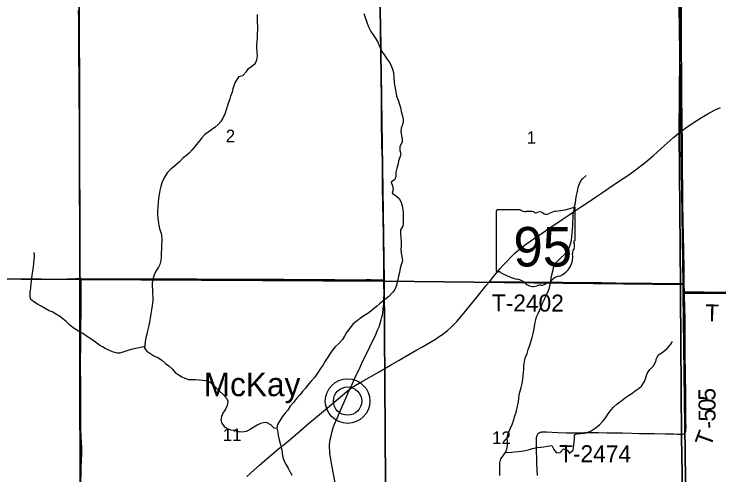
# Model space of a CAD drawing. Extents: x 1874609 to 2204689, y 815661 to 1281160.
# Drawn here: x 2033877 to 2046303, y 984416 to 992539 of the extents above; entities that cross this region are included whole.
import ezdxf

# ---------------------------------------------------------------- set-up
doc = ezdxf.new("R2010")
doc.units = 0
for name, color, linetype in [('GM_X_County_Road', 7, 'Continuous'), ('GM_X_Minor_River', 7, 'Continuous'), ('GM_X_Section', 7, 'Continuous'), ('GM_X_Section_Text', 7, 'Continuous'), ('GM_X_State_Location', 7, 'Continuous'), ('GM_X_State_Route', 7, 'Continuous'), ('GM_X_State_Shield', 7, 'Continuous'), ('GM_X_Township', 7, 'Continuous'), ('GM_X_Township_Road', 7, 'Continuous'), ('GM_X_Township_Road_Text', 7, 'Continuous'), ('GM_X_Unincorporated', 7, 'Continuous'), ('GM_X_Unincorporated_Location', 7, 'Continuous'), ('GM_X_Unincorporated_Text', 7, 'Continuous')]:
    doc.layers.add(name, color=color, linetype=linetype)

msp = doc.modelspace()

# ---------------------------------------------------------------- linework, layer by layer
at = {"layer": 'GM_X_County_Road'}
for points in [[(2033785, 987871), (2033999, 987869), (2034163, 987866), (2034261, 987865), (2034360, 987865), (2034441, 987864), (2034523, 987865), (2034670, 987868), (2034966, 987876), (2035031, 987876), (2035056, 987875)], [(2035056, 987875), (2035080, 987874), (2035179, 987872), (2035326, 987872), (2035457, 987872), (2035603, 987873), (2035766, 987874), (2035848, 987874), (2035930, 987874), (2036110, 987873), (2036241, 987871), (2036323, 987871), (2036438, 987870), (2036586, 987870), (2036766, 987871), (2036848, 987871), (2036995, 987871), (2037093, 987870), (2037224, 987868), (2037388, 987867), (2037551, 987866), (2037714, 987864), (2037812, 987865), (2037894, 987868), (2038024, 987867), (2038106, 987866), (2038171, 987866), (2038221, 987867), (2038286, 987867), (2038417, 987866), (2038629, 987864), (2038776, 987863), (2038924, 987862), (2039104, 987860), (2039186, 987859), (2039382, 987858), (2039529, 987858), (2039775, 987857), (2039922, 987857), (2040086, 987858), (2040168, 987858), (2040283, 987857), (2040365, 987856), (2040397, 987856)]]:
    msp.add_lwpolyline(points, dxfattribs=at)
at = {"layer": 'GM_X_Minor_River'}
for points in [[(2037838, 991439), (2037910, 991457), (2037972, 991528), (2038012, 991578), (2038066, 991624), (2038133, 991672), (2038159, 991733), (2038169, 991801), (2038161, 991877), (2038154, 991943), (2038156, 991995), (2038162, 992055), (2038169, 992127), (2038171, 992194), (2038173, 992262), (2038173, 992326), (2038168, 992394), (2038166, 992462), (2038166, 992530)], [(2040041, 992547), (2040071, 992459), (2040095, 992397), (2040128, 992313), (2040166, 992233), (2040206, 992173), (2040255, 992105), (2040297, 992031), (2040335, 991933), (2040360, 991879), (2040406, 991813), (2040448, 991751), (2040501, 991679), (2040523, 991625), (2040551, 991569), (2040565, 991507), (2040574, 991415), (2040576, 991337), (2040582, 991285), (2040593, 991235), (2040605, 991167), (2040619, 991091), (2040649, 991021), (2040674, 990945), (2040688, 990895), (2040704, 990825), (2040719, 990765), (2040735, 990688), (2040735, 990634), (2040719, 990576), (2040700, 990526), (2040696, 990468), (2040708, 990394), (2040720, 990332), (2040717, 990280), (2040679, 990205), (2040679, 990137), (2040693, 990077), (2040686, 990027), (2040652, 989955), (2040648, 989899), (2040623, 989824), (2040609, 989750), (2040607, 989676), (2040591, 989626), (2040526, 989576), (2040546, 989513), (2040558, 989445), (2040542, 989383), (2040617, 989331), (2040667, 989290), (2040699, 989224), (2040721, 989159), (2040730, 989097), (2040734, 989041), (2040736, 988987), (2040738, 988915), (2040737, 988855), (2040729, 988803), (2040691, 988735), (2040687, 988670), (2040694, 988604), (2040700, 988520), (2040700, 988448), (2040693, 988388), (2040703, 988324), (2040715, 988268), (2040722, 988188), (2040706, 988137), (2040686, 988061), (2040670, 987985), (2040657, 987917), (2040645, 987865), (2040633, 987809), (2040615, 987744), (2040588, 987686), (2040554, 987636), (2040486, 987562), (2040408, 987503)], [(2037838, 991439), (2037773, 991340), (2037753, 991274), (2037733, 991222), (2037719, 991164), (2037694, 991095), (2037678, 991043), (2037644, 990943), (2037616, 990851), (2037598, 990795), (2037558, 990707), (2037524, 990646), (2037475, 990594), (2037419, 990548), (2037359, 990498), (2037299, 990456), (2037241, 990414), (2037185, 990360), (2037124, 990278), (2037060, 990200), (2037016, 990145), (2036972, 990095), (2036922, 990053), (2036857, 990005), (2036791, 989937), (2036707, 989861), (2036641, 989803), (2036574, 989739), (2036528, 989664), (2036484, 989566), (2036462, 989498), (2036448, 989430), (2036432, 989362), (2036422, 989294), (2036418, 989215), (2036411, 989139), (2036407, 989061), (2036407, 989007), (2036409, 988951), (2036417, 988888), (2036427, 988820), (2036443, 988752), (2036469, 988676), (2036479, 988592), (2036479, 988542), (2036473, 988465), (2036473, 988399), (2036471, 988325), (2036471, 988253), (2036464, 988197), (2036444, 988127), (2036424, 988076), (2036378, 988010), (2036344, 987944), (2036322, 987864), (2036312, 987802), (2036310, 987740), (2036314, 987687), (2036318, 987609), (2036321, 987551), (2036321, 987487), (2036311, 987401), (2036301, 987325), (2036289, 987254), (2036277, 987182), (2036261, 987106), (2036253, 987048), (2036229, 986954), (2036214, 986900), (2036200, 986835), (2036190, 986769), (2036182, 986705), (2036178, 986653), (2036214, 986595), (2036268, 986563), (2036338, 986518), (2036410, 986486), (2036478, 986442), (2036547, 986382), (2036603, 986338), (2036661, 986284), (2036717, 986224), (2036785, 986173), (2036835, 986143), (2036885, 986119), (2036949, 986099), (2037017, 986097), (2037075, 986097), (2037141, 986093), (2037198, 986087), (2037258, 986081), (2037316, 986065), (2037378, 986017), (2037428, 985961), (2037490, 985898), (2037562, 985836), (2037622, 985770), (2037646, 985716), (2037632, 985640), (2037596, 985565), (2037558, 985503)], [(2043022, 986888), (2043038, 986964), (2043050, 987024), (2043059, 987078), (2043073, 987149), (2043089, 987201), (2043115, 987259), (2043146, 987327), (2043170, 987383), (2043194, 987446), (2043226, 987512), (2043257, 987582), (2043293, 987650), (2043315, 987713), (2043331, 987775), (2043338, 987825), (2043348, 987889), (2043358, 987945), (2043374, 988005), (2043389, 988066), (2043405, 988118), (2043437, 988168), (2043511, 988238), (2043592, 988313), (2043632, 988369), (2043664, 988419), (2043688, 988487), (2043703, 988554), (2043713, 988614), (2043717, 988682), (2043723, 988740), (2043726, 988814), (2043728, 988874), (2043732, 988942), (2043736, 989005), (2043743, 989059), (2043759, 989145), (2043773, 989215), (2043781, 989265), (2043786, 989317), (2043802, 989388), (2043814, 989450), (2043830, 989504), (2043865, 989586), (2043899, 989636), (2043965, 989695)], [(2036180, 986679), (2036162, 986675), (2036108, 986663), (2036050, 986649), (2035962, 986631), (2035899, 986617), (2035829, 986591), (2035743, 986563), (2035691, 986563), (2035611, 986585), (2035549, 986613), (2035485, 986645), (2035435, 986671), (2035382, 986705), (2035312, 986756), (2035232, 986814), (2035156, 986864), (2035086, 986910), (2035010, 986952), (2034936, 986996), (2034866, 987049), (2034792, 987121), (2034738, 987169), (2034674, 987219), (2034623, 987245), (2034547, 987291), (2034495, 987311), (2034425, 987350), (2034351, 987390), (2034291, 987428), (2034227, 987470), (2034167, 987512), (2034159, 987566), (2034161, 987638), (2034169, 987709), (2034179, 987789), (2034189, 987883), (2034195, 987937), (2034207, 988009), (2034220, 988087), (2034226, 988142), (2034230, 988218), (2034234, 988274), (2034232, 988338)], [(2040408, 987503), (2040321, 987433), (2040267, 987384), (2040197, 987326), (2040113, 987260), (2040045, 987219), (2039983, 987181), (2039926, 987135), (2039856, 987078), (2039794, 987002), (2039740, 986928), (2039703, 986861), (2039665, 986803), (2039601, 986733), (2039539, 986676), (2039484, 986610), (2039450, 986554), (2039408, 986489), (2039364, 986421), (2039327, 986359), (2039293, 986307), (2039217, 986194), (2039179, 986142), (2039116, 986069), (2039072, 986019), (2039012, 985945), (2038964, 985887), (2038913, 985828), (2038857, 985762), (2038801, 985694), (2038743, 985625), (2038700, 985559), (2038654, 985505), (2038602, 985438), (2038519, 985302), (2038507, 985242), (2038529, 985168), (2038535, 985109), (2038552, 985037), (2038570, 984967), (2038582, 984917), (2038597, 984861), (2038603, 984801), (2038613, 984723), (2038647, 984649), (2038676, 984595), (2038706, 984537), (2038744, 984465), (2038771, 984413)], [(2042438, 984407), (2042442, 984467), (2042440, 984521), (2042440, 984577), (2042441, 984629), (2042461, 984702), (2042501, 984754), (2042535, 984808), (2042565, 984866), (2042576, 984938), (2042576, 985003), (2042572, 985065), (2042579, 985123), (2042605, 985189), (2042627, 985243), (2042657, 985307), (2042686, 985388), (2042702, 985438), (2042726, 985520), (2042757, 985649), (2042767, 985707), (2042777, 985761), (2042783, 985819), (2042792, 985875), (2042814, 985955), (2042834, 986028), (2042847, 986102), (2042855, 986164), (2042859, 986214), (2042863, 986280), (2042866, 986344), (2042874, 986416), (2042892, 986489), (2042920, 986557), (2042943, 986629), (2042963, 986687), (2042989, 986760), (2043010, 986836), (2043022, 986888)], [(2042538, 984815), (2042571, 984814), (2042649, 984819), (2042701, 984825), (2042763, 984831), (2042815, 984837), (2042895, 984846), (2042965, 984864), (2043019, 984882), (2043097, 984898), (2043165, 984905), (2043219, 984909), (2043281, 984923), (2043355, 984935), (2043391, 984863), (2043439, 984806), (2043507, 984810), (2043563, 984874), (2043627, 984854), (2043667, 984800), (2043733, 984855), (2043745, 984947), (2043753, 984999), (2043758, 985055), (2043760, 985123), (2043812, 985146), (2043862, 985144), (2043932, 985150), (2043998, 985168), (2044052, 985193), (2044122, 985243), (2044196, 985297), (2044263, 985370), (2044311, 985430), (2044351, 985492), (2044401, 985563), (2044444, 985613), (2044508, 985671), (2044590, 985728), (2044656, 985780), (2044710, 985818), (2044767, 985853), (2044829, 985897), (2044881, 985933), (2044937, 985981), (2044989, 986060), (2045014, 986126), (2045038, 986202), (2045086, 986275), (2045152, 986337), (2045191, 986415), (2045203, 986469), (2045239, 986532), (2045321, 986588), (2045398, 986650), (2045458, 986719), (2045488, 986769)], [(2037558, 985503), (2037532, 985447), (2037521, 985387), (2037539, 985327), (2037581, 985267), (2037644, 985231), (2037698, 985211), (2037756, 985204), (2037849, 985175)], [(2038508, 985237), (2038461, 985243), (2038401, 985301), (2038326, 985339), (2038272, 985337), (2038220, 985321), (2038162, 985294), (2038103, 985256), (2038041, 985214), (2037971, 985181), (2037905, 985171), (2037849, 985175)]]:
    msp.add_lwpolyline(points, dxfattribs=at)
at = {"layer": 'GM_X_Section'}
for points in [[(2029677, 993105), (2035022, 993074), (2035033, 987863), (2029642, 987908)], [(2035022, 993074), (2040325, 993064), (2040399, 987834), (2035033, 987863)], [(2040325, 993064), (2045597, 993088), (2045674, 987772), (2040399, 987834)], [(2045597, 993088), (2050738, 993114), (2050843, 987600), (2045675, 987622), (2045674, 987772)], [(2035033, 987863), (2035040, 982545), (2029723, 982510), (2029642, 987908)], [(2035033, 987863), (2040399, 987834), (2040436, 982497), (2035040, 982545)], [(2040399, 987834), (2045674, 987772), (2045675, 987622), (2045737, 982456), (2040436, 982497)], [(2045675, 987622), (2050843, 987600), (2050888, 982296), (2045739, 982288), (2045737, 982456)]]:
    msp.add_lwpolyline(points, close=True, dxfattribs=at)
at = {"layer": 'GM_X_State_Route'}
for points in [[(2040397, 987798), (2040397, 987856), (2040397, 987901), (2040393, 988065), (2040393, 988180), (2040393, 988278), (2040390, 988442), (2040389, 988573), (2040388, 988672), (2040385, 988901), (2040382, 989015), (2040380, 989097), (2040378, 989228), (2040374, 989458), (2040372, 989605), (2040374, 989753), (2040374, 989851), (2040371, 989949), (2040364, 990113), (2040363, 990211), (2040363, 990310), (2040361, 990391), (2040357, 990506), (2040354, 990637), (2040355, 990818), (2040359, 991015), (2040359, 991080), (2040358, 991194), (2040356, 991375), (2040351, 991604), (2040349, 991801), (2040349, 991965), (2040346, 992080), (2040343, 992195), (2040341, 992326), (2040339, 992555)], [(2039797, 985930), (2039832, 985955), (2039888, 985991), (2040001, 986057), (2040315, 986236), (2040414, 986293), (2040513, 986349), (2040668, 986441), (2040838, 986538), (2040979, 986620), (2041064, 986669), (2041206, 986751), (2041305, 986809), (2041374, 986854), (2041427, 986891), (2041466, 986920), (2041517, 986962), (2041577, 987016), (2041624, 987062), (2041680, 987121), (2041745, 987195), (2041860, 987334), (2042015, 987525), (2042202, 987754), (2042256, 987820), (2042336, 987920), (2042441, 988046), (2042495, 988108), (2042551, 988168), (2042643, 988262), (2042713, 988331), (2042774, 988385), (2042826, 988427), (2042891, 988476), (2042985, 988543), (2043052, 988589), (2043121, 988635), (2043202, 988690), (2043310, 988764), (2043446, 988854), (2043541, 988918), (2043664, 989001), (2043759, 989065), (2043881, 989148), (2044032, 989248), (2044127, 989311), (2044235, 989384), (2044532, 989587), (2044614, 989641), (2044695, 989695), (2044803, 989770), (2044882, 989828), (2044973, 989899), (2045074, 989982), (2045148, 990046), (2045344, 990222), (2045503, 990364), (2045578, 990427), (2045643, 990478), (2045658, 990489), (2045723, 990536), (2045831, 990610), (2045913, 990665), (2045997, 990717), (2046111, 990782), (2046227, 990843), (2046330, 990893)], [(2040022, 986414), (2040059, 986493), (2040153, 986685), (2040253, 986892), (2040286, 986966), (2040311, 987027), (2040332, 987089), (2040351, 987151), (2040363, 987199), (2040375, 987263), (2040385, 987344), (2040393, 987426), (2040397, 987508), (2040399, 987606), (2040398, 987770), (2040397, 987798)], [(2039797, 985930), (2039817, 985973), (2039885, 986122), (2039976, 986315), (2040022, 986414)], [(2037982, 984388), (2038104, 984498), (2038201, 984586), (2038300, 984672), (2038375, 984735), (2038463, 984809), (2038538, 984873), (2038638, 984955), (2038789, 985082), (2038914, 985188), (2039064, 985314), (2039189, 985421), (2039402, 985600), (2039741, 985885), (2039792, 985926), (2039797, 985930)], [(2039544, 984247), (2039479, 984585), (2039454, 984731), (2039445, 984796), (2039441, 984845), (2039439, 984895), (2039440, 984944), (2039445, 984993), (2039452, 985042), (2039465, 985107), (2039486, 985186), (2039505, 985249), (2039528, 985311), (2039572, 985417), (2039645, 985583), (2039692, 985687), (2039763, 985853), (2039797, 985930)]]:
    msp.add_lwpolyline(points, dxfattribs=at)
at = {"layer": 'GM_X_State_Shield'}
for p, q in [((2042379, 989073), (2042379, 988016)), ((2042801, 989091), (2042393, 989091)), ((2043771, 988565), (2043771, 989117)), ((2043771, 988565), (2043771, 988565))]:
    msp.add_line(p, q, dxfattribs=at)
for centre, radius, start, end in [((2042395, 989075), 16.1, 98.1301, 188.1301), ((2042898, 989214), 156, 231.6195, 271.1119), ((2042950, 988498), 562, 80.4867, 94.9883), ((2043077, 989081), 45.1, 219.7921, 297.1024), ((2043143, 988959), 93.8, 54.4667, 119.1411), ((2043464, 988768), 297, 97.3462, 120.7689), ((2043276, 990532), 1476, 275.8445, 288.9065), ((2043756, 989120), 15.5, 351.8621, 97.738), ((2043265, 989126), 113, 233.8562, 294.8282), ((2043755, 988563), 16.6, 289.6038, 7.7341), ((2043768, 988524), 24, 107.944, 210.337), ((2043615, 988454), 144, 340.033, 23.6496), ((2043358, 988263), 369, 292.3089, 8.9858), ((2043827, 988333), 105, 136.8065, 186.9296), ((2042395, 988014), 16.3, 171.9584, 258.3066), ((2042398, 988122), 124, 267.339, 280.6039), ((2042423, 987955), 44.8, 29.7484, 93.2717), ((2042989, 988905), 1066, 240.4129, 257.1985), ((2042671, 987542), 334, 47.1842, 75.836), ((2043258, 987914), 119, 282.8732, 323.2771), ((2043514, 987720), 202, 94.4031, 142.5768), ((2043031, 987950), 212, 230.7004, 286.2918), ((2043154, 987585), 174, 85.6951, 111.2099), ((2043169, 987871), 113, 268.777, 315.5493), ((2043271, 987769), 31.8, 65.7517, 132.6484)]:
    msp.add_arc(centre, radius, start, end, dxfattribs=at)
at = {"layer": 'GM_X_Township'}
for points in [[(2013226, 970636), (2013158, 976319), (2013145, 977956), (2013122, 980772), (2013088, 985095), (2013083, 985682), (2013045, 990449), (2013055, 993227), (2019008, 993199), (2023012, 993180), (2027008, 993161), (2032163, 993089), (2034988, 993049), (2040325, 993088), (2045626, 993121), (2045602, 990454), (2045625, 987740), (2045624, 987592), (2045643, 985092), (2045777, 977423), (2045852, 971713)], [(2048367, 971741), (2045852, 971713), (2045777, 977423), (2045643, 985092), (2045624, 987592), (2045625, 987740), (2045602, 990454), (2045626, 993121), (2050693, 993155)]]:
    msp.add_lwpolyline(points, dxfattribs=at)
at = {"layer": 'GM_X_Township_Road'}
for points in [[(2045658, 990489), (2045658, 990597), (2045655, 990778), (2045651, 990991), (2045649, 991254), (2045648, 991336), (2045650, 991369), (2045648, 991598), (2045645, 991795), (2045644, 991926), (2045645, 992074), (2045646, 992255), (2045646, 992435), (2045643, 992550), (2045641, 992632), (2045639, 992747), (2045637, 992846), (2045633, 992977), (2045632, 993043), (2045631, 993075), (2045630, 993099), (2045630, 993105)], [(2035056, 987875), (2035052, 987882), (2035047, 987892), (2035043, 987901), (2035042, 987911), (2035041, 987922), (2035041, 987941), (2035043, 988026), (2035044, 988108), (2035043, 988173), (2035042, 988238), (2035043, 988304), (2035042, 988386), (2035041, 988533), (2035041, 988894), (2035041, 989075), (2035041, 989255), (2035039, 989403), (2035038, 989501), (2035036, 989715), (2035038, 989912), (2035037, 990059), (2035034, 990256), (2035032, 990338), (2035030, 990469), (2035029, 990649), (2035027, 990797), (2035026, 990945), (2035026, 991125), (2035023, 991420), (2035021, 991568), (2035020, 991666), (2035018, 991896), (2035016, 992109), (2035016, 992273), (2035015, 992454), (2035014, 992601)], [(2045692, 987789), (2045691, 987873), (2045689, 988053), (2045683, 988349), (2045678, 988661), (2045674, 988874), (2045672, 988973), (2045670, 989120), (2045668, 989284), (2045666, 989465), (2045665, 989531), (2045662, 989727), (2045662, 989826), (2045662, 989924), (2045661, 990039), (2045661, 990187), (2045662, 990252), (2045661, 990302), (2045660, 990416), (2045658, 990466), (2045658, 990489)], [(2035055, 986780), (2035056, 986803), (2035056, 986885), (2035056, 986950), (2035056, 987048), (2035056, 987114), (2035057, 987195), (2035057, 987390), (2035057, 987472), (2035058, 987553), (2035059, 987734), (2035060, 987781), (2035059, 987843), (2035056, 987875)], [(2042256, 987820), (2042306, 987820), (2042388, 987820), (2042486, 987819), (2042649, 987818), (2042812, 987817), (2042926, 987816), (2043007, 987815), (2043106, 987815), (2043270, 987815), (2043352, 987814), (2043450, 987813), (2043549, 987813), (2043860, 987810), (2044073, 987807), (2044237, 987806), (2044401, 987804), (2044483, 987803), (2044663, 987799), (2044860, 987798), (2045123, 987796), (2045303, 987793), (2045418, 987793), (2045549, 987793), (2045631, 987790), (2045684, 987789), (2045692, 987789)], [(2045696, 987645), (2045693, 987774), (2045692, 987789)], [(2045697, 985145), (2045709, 985156), (2045716, 985171), (2045720, 985186), (2045722, 985203), (2045724, 985252), (2045723, 985350), (2045723, 985465), (2045722, 985547), (2045722, 985613), (2045721, 985678), (2045720, 985809), (2045719, 985874), (2045718, 985956), (2045717, 986071), (2045717, 986137), (2045715, 986202), (2045713, 986284), (2045711, 986448), (2045710, 986514), (2045709, 986596), (2045708, 986678), (2045710, 986776), (2045711, 986858), (2045709, 986973), (2045709, 987022), (2045709, 987071), (2045709, 987120), (2045707, 987218), (2045704, 987315), (2045701, 987430), (2045699, 987496), (2045696, 987645)], [(2045696, 987645), (2045733, 987645), (2045861, 987643), (2045959, 987643), (2046041, 987642), (2046172, 987640), (2046369, 987639), (2046517, 987641), (2046681, 987642), (2046895, 987641), (2047010, 987641), (2047157, 987642), (2047338, 987641), (2047469, 987641), (2047797, 987641), (2048126, 987640), (2048198, 987639)], [(2035056, 984296), (2035059, 984444), (2035062, 984558), (2035069, 984787), (2035068, 984885), (2035063, 985000), (2035060, 985081), (2035055, 985229), (2035055, 985295), (2035055, 985360), (2035055, 985392), (2035053, 985441), (2035053, 985459), (2035053, 985479), (2035054, 985501), (2035054, 985529), (2035054, 985548), (2035054, 985577), (2035054, 985604), (2035054, 985638), (2035054, 985664), (2035054, 985697), (2035054, 985762), (2035053, 985908), (2035052, 985989), (2035051, 986103), (2035049, 986233), (2035049, 986282), (2035048, 986444), (2035048, 986474), (2035049, 986499), (2035049, 986525), (2035051, 986590), (2035052, 986640), (2035053, 986705), (2035054, 986754), (2035055, 986780)], [(2043103, 984406), (2043101, 984504), (2043095, 984619), (2043091, 984717), (2043088, 984831), (2043087, 984930), (2043087, 985012), (2043089, 985061), (2043090, 985077), (2043093, 985093), (2043098, 985109), (2043104, 985124), (2043113, 985138), (2043124, 985150), (2043137, 985160), (2043152, 985167), (2043167, 985172), (2043183, 985175), (2043200, 985176), (2043265, 985173), (2043462, 985164), (2043609, 985157), (2043658, 985156), (2043757, 985156), (2043838, 985158), (2043937, 985162), (2044019, 985163), (2044100, 985164), (2044182, 985163), (2044327, 985160), (2044409, 985159), (2044491, 985158)], [(2044491, 985158), (2044507, 985158), (2044605, 985155), (2044769, 985150), (2044900, 985146), (2045048, 985144), (2045163, 985144), (2045359, 985142), (2045507, 985139), (2045569, 985137), (2045646, 985137), (2045661, 985136), (2045681, 985139), (2045697, 985145)]]:
    msp.add_lwpolyline(points, dxfattribs=at)
at = {"layer": 'GM_X_Unincorporated'}
for radius in [393, 249]:
    msp.add_circle((2039756, 985717), radius, dxfattribs=at)
at = {"layer": 'GM_X_Unincorporated_Location'}
msp.add_line((2039756, 985717), (2039756, 985717), dxfattribs=at)

# ---------------------------------------------------------------- texts
at = {"layer": 'GM_X_Section_Text'}
for s, p in [('2', (2037609, 990281)), ('1', (2042916, 990253)), ('11', (2037557, 985013)), ('12', (2042306, 984961))]:
    msp.add_text(s, height=221, rotation=0, dxfattribs=at).set_placement(p)
at = {"layer": 'GM_X_State_Location'}
for s in ['s', 'r']:
    msp.add_text(s, height=1, dxfattribs=at).set_placement((2043060, 988474))
msp.add_text('95', height=1, rotation=0, dxfattribs=at).set_placement((2042808, 988402))
at = {"layer": 'GM_X_State_Shield'}
msp.add_text('95', height=696.1, dxfattribs=at).set_placement((2042680, 988091))
at = {"layer": 'GM_X_Township_Road_Text'}
for s, rotation, p in [('T-2402', 359.7652, (2042298, 987299)), ('T', 358.95, (2046059, 987123)), ('5', 90.3103, (2046243, 985726)), ('0', 90.2723, (2046244, 985541)), ('5', 90.1301, (2046244, 985356)), ('-', 93.5823, (2046252, 985238)), ('T', 69.9792, (2046156, 984894)), ('T-2474', 359.7658, (2043483, 984641))]:
    msp.add_text(s, height=300, rotation=rotation, dxfattribs=at).set_placement(p)
at = {"layer": 'GM_X_Unincorporated_Text'}
msp.add_text('McKay', height=417, rotation=0, dxfattribs=at).set_placement((2037220, 985804))

doc.saveas('drawing.dxf')
